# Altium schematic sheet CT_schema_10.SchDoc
size 254 x 194 mm
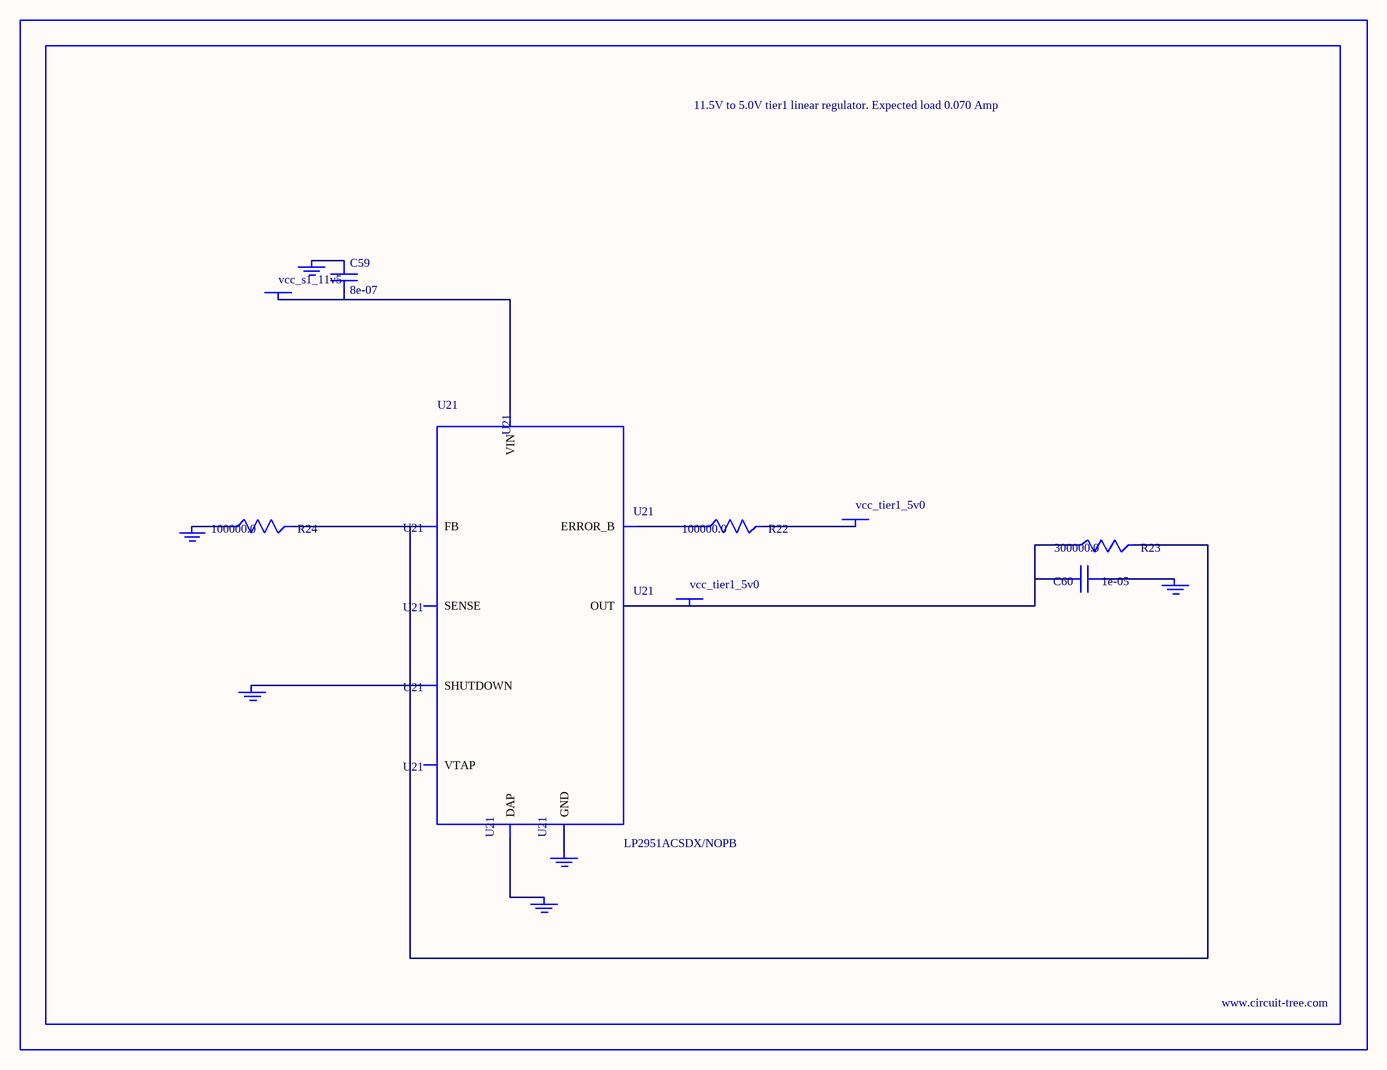
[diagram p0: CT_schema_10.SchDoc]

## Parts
BORDER9  (no value)
C59  8e-07  [R0603]
C60  1e-05  [C1210]
GND_INSTANCE_9_0  (no value)
GND_INSTANCE_9_1  (no value)
GND_INSTANCE_9_2  (no value)
GND_INSTANCE_9_3  (no value)
GND_INSTANCE_9_4  (no value)
GND_INSTANCE_9_5  (no value)
POWER_INSTANCE_9_0  vcc_tier1_5v0
POWER_INSTANCE_9_1  vcc_s1_11v5
POWER_INSTANCE_9_2  vcc_tier1_5v0
R22  100000.0  [R0603]
R23  300000.0  [R0603]
R24  100000.0  [R0603]
U21  LP2951ACSDX/NOPB  [WSON-8]

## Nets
NetC59_1: C59.1 GND_INSTANCE_9_3.0(GND)
NetC59_2: C59.2 POWER_INSTANCE_9_1.0(PWR) U21.8(VIN)
NetC60_1: C60.1 GND_INSTANCE_9_0.0(GND)
NetC60_2: C60.2 POWER_INSTANCE_9_2.0(PWR) R23.1 U21.1(OUT)
NetGND_INSTANCE_9_1_0: GND_INSTANCE_9_1.0(GND) U21.3(SHUTDOWN)
NetGND_INSTANCE_9_2_0: GND_INSTANCE_9_2.0(GND) R24.1
NetGND_INSTANCE_9_4_0: GND_INSTANCE_9_4.0(GND) U21.PAD(DAP)
NetGND_INSTANCE_9_5_0: GND_INSTANCE_9_5.0(GND) U21.4(GND)
NetPOWER_INSTANCE_9_0_0: POWER_INSTANCE_9_0.0(PWR) R22.2
NetR22_1: R22.1 U21.5(ERROR_B)
NetR23_2: R23.2 R24.2 U21.7(FB)

Not connected (* = marked no-connect by the designer): U21 2(SENSE) 6(VTAP)

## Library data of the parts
BORDER9 = BORDER_PAGE9
C59 = C59
C60 = GRM32DR61E106MA12L
GND_INSTANCE_9_0-GND_INSTANCE_9_5 = GND
POWER_INSTANCE_9_0-POWER_INSTANCE_9_2 = PWR
R22 R24 = RC0603JR-07100KL
R23 = RC0603JR-07300KL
